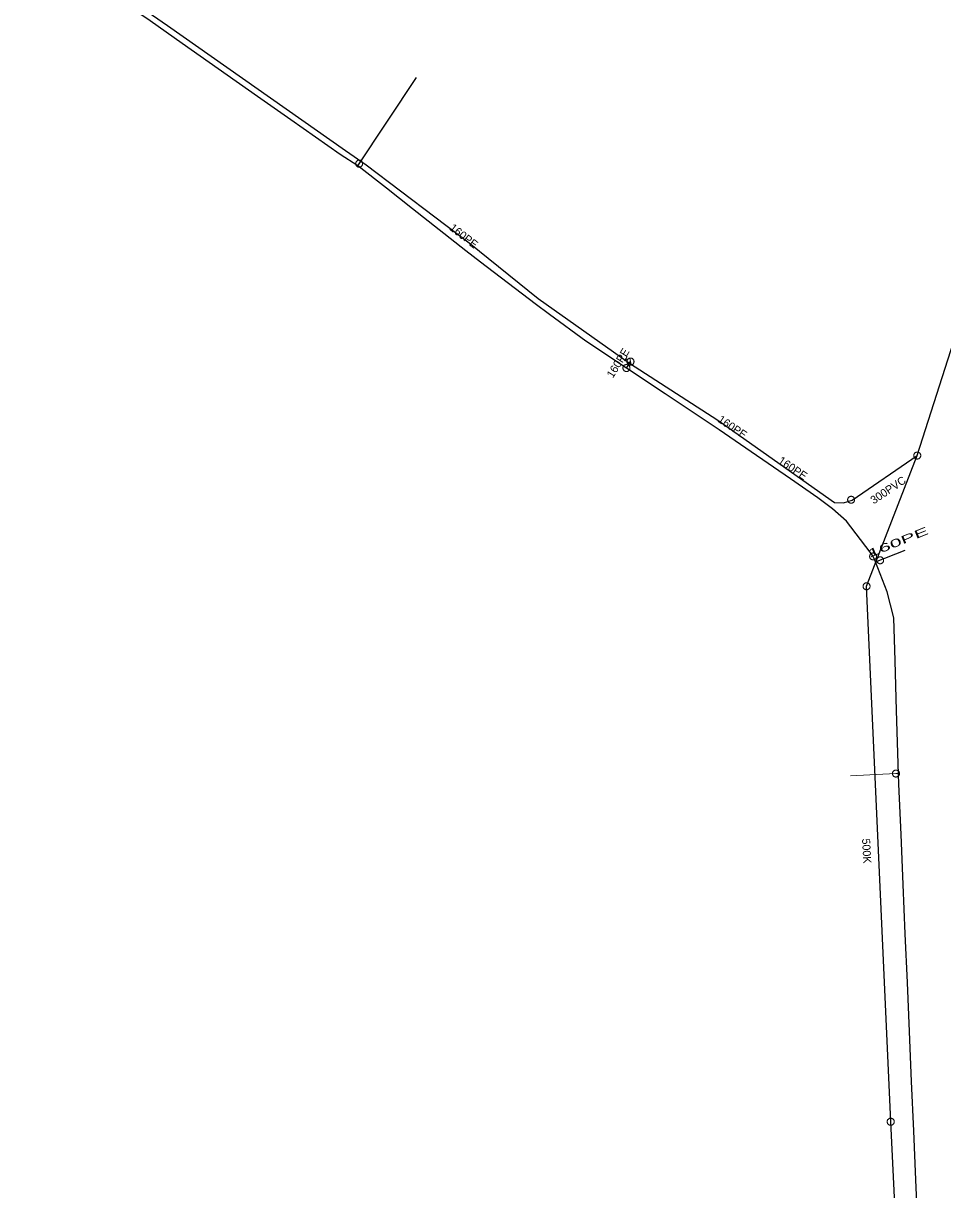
# Model space of a CAD drawing. Extents: x -741806 to -738704, y -1059275 to -1055387.
# Drawn here: x -740278.7 to -740163.8, y -1056238.7 to -1056093 of the extents above; entities that cross this region are included whole.
import ezdxf

# ---------------------------------------------------------------- set-up
doc = ezdxf.new("R2010")
doc.units = 0
doc.header["$LTSCALE"] = 0.4
for name, color, linetype, lineweight in [('2', 7, 'Continuous', 25), ('21', 7, 'Continuous', 13), ('3', 7, 'Continuous', 13), ('50', 7, 'Continuous', 13), ('51', 7, 'Continuous', 13), ('52', 7, 'Continuous', 25)]:
    doc.layers.add(name, color=color, linetype=linetype, lineweight=lineweight)
doc.layers.add('5', color=7, linetype='Continuous')
doc.layers.add('53', color=7, linetype='Continuous')

msp = doc.modelspace()

# ---------------------------------------------------------------- linework, layer by layer
at = {"layer": '2'}
msp.add_line((-740175.09, -1056152.54), (-740166.94, -1056146.97), dxfattribs=at)
for points in [[(-740347.69, -1055992.02), (-740330.71, -1056025.94), (-740324.879, -1056035.399), (-740312.55, -1056051.09), (-740298.309, -1056065.56), (-740282.969, -1056077.85), (-740260.67, -1056093.22), (-740238.399, -1056108.84), (-740235.84, -1056110.649), (-740222.969, -1056120.379), (-740214.329, -1056127.35), (-740202.93, -1056135.429), (-740191.883, -1056142.544), (-740177.289, -1056152.83), (-740176.145, -1056152.872), (-740175.09, -1056152.54)], [(-740156.993, -1056330.193), (-740165.539, -1056330.419), (-740167.3, -1056291.23), (-740170.26, -1056230.22), (-740173.28, -1056163.31), (-740166.94, -1056146.97), (-740157.149, -1056116.429)]]:
    msp.add_lwpolyline(points, dxfattribs=at)
at = {"layer": '21'}
msp.add_lwpolyline([(-740169.288, -1056186.703), (-740169.602, -1056186.713), (-740175.287, -1056187.003)], dxfattribs=at)
at = {"layer": '3'}
for points in [[(-740166.502, -1056146.97), (-740166.504, -1056146.925), (-740166.512, -1056146.88), (-740166.524, -1056146.835), (-740166.539, -1056146.793), (-740166.561, -1056146.752), (-740166.585, -1056146.713), (-740166.615, -1056146.678), (-740166.647, -1056146.645), (-740166.683, -1056146.617), (-740166.72, -1056146.592), (-740166.762, -1056146.571), (-740166.804, -1056146.554), (-740166.848, -1056146.543), (-740166.894, -1056146.535), (-740166.94, -1056146.533), (-740166.985, -1056146.535), (-740167.031, -1056146.543), (-740167.075, -1056146.554), (-740167.117, -1056146.571), (-740167.159, -1056146.592), (-740167.196, -1056146.617), (-740167.232, -1056146.645), (-740167.264, -1056146.678), (-740167.294, -1056146.713), (-740167.318, -1056146.752), (-740167.338, -1056146.793), (-740167.355, -1056146.835), (-740167.367, -1056146.88), (-740167.375, -1056146.925), (-740167.377, -1056146.971), (-740167.375, -1056147.016), (-740167.367, -1056147.061), (-740167.355, -1056147.106), (-740167.338, -1056147.149), (-740167.318, -1056147.189), (-740167.294, -1056147.228), (-740167.264, -1056147.263), (-740167.232, -1056147.296), (-740167.196, -1056147.324), (-740167.159, -1056147.349), (-740167.117, -1056147.37), (-740167.075, -1056147.387), (-740167.031, -1056147.399), (-740166.985, -1056147.406), (-740166.94, -1056147.408), (-740166.894, -1056147.406), (-740166.848, -1056147.399), (-740166.804, -1056147.387), (-740166.762, -1056147.37), (-740166.72, -1056147.349), (-740166.683, -1056147.324), (-740166.647, -1056147.296), (-740166.615, -1056147.263), (-740166.585, -1056147.228), (-740166.561, -1056147.189), (-740166.539, -1056147.148), (-740166.524, -1056147.106), (-740166.512, -1056147.061), (-740166.504, -1056147.016), (-740166.502, -1056146.971)], [(-740174.768, -1056152.5), (-740174.771, -1056152.455), (-740174.778, -1056152.41), (-740174.79, -1056152.365), (-740174.806, -1056152.323), (-740174.827, -1056152.282), (-740174.852, -1056152.243), (-740174.881, -1056152.208), (-740174.913, -1056152.175), (-740174.949, -1056152.147), (-740174.987, -1056152.122), (-740175.028, -1056152.101), (-740175.071, -1056152.084), (-740175.115, -1056152.073), (-740175.16, -1056152.065), (-740175.206, -1056152.063), (-740175.252, -1056152.065), (-740175.297, -1056152.073), (-740175.341, -1056152.084), (-740175.384, -1056152.101), (-740175.425, -1056152.122), (-740175.463, -1056152.147), (-740175.498, -1056152.175), (-740175.531, -1056152.208), (-740175.56, -1056152.243), (-740175.585, -1056152.282), (-740175.605, -1056152.323), (-740175.622, -1056152.365), (-740175.634, -1056152.41), (-740175.641, -1056152.455), (-740175.643, -1056152.501), (-740175.641, -1056152.546), (-740175.634, -1056152.591), (-740175.622, -1056152.636), (-740175.605, -1056152.679), (-740175.585, -1056152.719), (-740175.56, -1056152.758), (-740175.531, -1056152.793), (-740175.498, -1056152.826), (-740175.463, -1056152.854), (-740175.425, -1056152.879), (-740175.384, -1056152.9), (-740175.341, -1056152.917), (-740175.297, -1056152.929), (-740175.252, -1056152.936), (-740175.206, -1056152.938), (-740175.16, -1056152.936), (-740175.115, -1056152.929), (-740175.071, -1056152.917), (-740175.028, -1056152.9), (-740174.987, -1056152.879), (-740174.949, -1056152.854), (-740174.913, -1056152.826), (-740174.881, -1056152.793), (-740174.852, -1056152.758), (-740174.827, -1056152.719), (-740174.806, -1056152.678), (-740174.79, -1056152.636), (-740174.778, -1056152.591), (-740174.771, -1056152.546), (-740174.768, -1056152.501)], [(-740172.842, -1056163.31), (-740172.845, -1056163.265), (-740172.852, -1056163.22), (-740172.864, -1056163.175), (-740172.88, -1056163.133), (-740172.901, -1056163.092), (-740172.926, -1056163.053), (-740172.955, -1056163.018), (-740172.987, -1056162.985), (-740173.023, -1056162.957), (-740173.061, -1056162.932), (-740173.102, -1056162.911), (-740173.145, -1056162.894), (-740173.189, -1056162.883), (-740173.234, -1056162.875), (-740173.28, -1056162.873), (-740173.326, -1056162.875), (-740173.371, -1056162.883), (-740173.415, -1056162.894), (-740173.458, -1056162.911), (-740173.499, -1056162.932), (-740173.537, -1056162.957), (-740173.572, -1056162.985), (-740173.605, -1056163.018), (-740173.634, -1056163.053), (-740173.659, -1056163.092), (-740173.679, -1056163.133), (-740173.696, -1056163.175), (-740173.708, -1056163.22), (-740173.715, -1056163.265), (-740173.717, -1056163.311), (-740173.715, -1056163.356), (-740173.708, -1056163.401), (-740173.696, -1056163.446), (-740173.679, -1056163.489), (-740173.659, -1056163.529), (-740173.634, -1056163.568), (-740173.605, -1056163.603), (-740173.572, -1056163.636), (-740173.537, -1056163.664), (-740173.499, -1056163.689), (-740173.458, -1056163.71), (-740173.415, -1056163.727), (-740173.371, -1056163.739), (-740173.326, -1056163.746), (-740173.28, -1056163.748), (-740173.234, -1056163.746), (-740173.189, -1056163.739), (-740173.145, -1056163.727), (-740173.102, -1056163.71), (-740173.061, -1056163.689), (-740173.023, -1056163.664), (-740172.987, -1056163.636), (-740172.955, -1056163.603), (-740172.926, -1056163.568), (-740172.901, -1056163.529), (-740172.88, -1056163.488), (-740172.864, -1056163.446), (-740172.852, -1056163.401), (-740172.845, -1056163.356), (-740172.842, -1056163.311)], [(-740169.822, -1056230.22), (-740169.825, -1056230.175), (-740169.832, -1056230.13), (-740169.844, -1056230.085), (-740169.86, -1056230.043), (-740169.881, -1056230.002), (-740169.906, -1056229.963), (-740169.935, -1056229.928), (-740169.967, -1056229.895), (-740170.003, -1056229.867), (-740170.041, -1056229.842), (-740170.082, -1056229.821), (-740170.125, -1056229.804), (-740170.169, -1056229.793), (-740170.214, -1056229.785), (-740170.26, -1056229.783), (-740170.306, -1056229.785), (-740170.351, -1056229.793), (-740170.395, -1056229.804), (-740170.438, -1056229.821), (-740170.479, -1056229.842), (-740170.517, -1056229.867), (-740170.552, -1056229.895), (-740170.585, -1056229.928), (-740170.614, -1056229.963), (-740170.639, -1056230.002), (-740170.659, -1056230.043), (-740170.676, -1056230.085), (-740170.688, -1056230.13), (-740170.695, -1056230.175), (-740170.697, -1056230.221), (-740170.695, -1056230.266), (-740170.688, -1056230.311), (-740170.676, -1056230.356), (-740170.659, -1056230.399), (-740170.639, -1056230.439), (-740170.614, -1056230.478), (-740170.585, -1056230.513), (-740170.552, -1056230.546), (-740170.517, -1056230.574), (-740170.479, -1056230.599), (-740170.438, -1056230.62), (-740170.395, -1056230.637), (-740170.351, -1056230.649), (-740170.306, -1056230.656), (-740170.26, -1056230.658), (-740170.214, -1056230.656), (-740170.169, -1056230.649), (-740170.125, -1056230.637), (-740170.082, -1056230.62), (-740170.041, -1056230.599), (-740170.003, -1056230.574), (-740169.967, -1056230.546), (-740169.935, -1056230.513), (-740169.906, -1056230.478), (-740169.881, -1056230.439), (-740169.86, -1056230.398), (-740169.844, -1056230.356), (-740169.832, -1056230.311), (-740169.825, -1056230.266), (-740169.822, -1056230.221)]]:
    msp.add_lwpolyline(points, dxfattribs=at)
at = {"layer": '50'}
for p, q in [((-740203.547, -1056135.127), (-740203.384, -1056134.865)), ((-740203.222, -1056134.605), (-740203.384, -1056134.865)), ((-740203.171, -1056134.998), (-740203.384, -1056134.865)), ((-740202.792, -1056135.234), (-740202.89, -1056134.801)), ((-740202.792, -1056135.234), (-740202.69, -1056135.671))]:
    msp.add_line(p, q, dxfattribs=at)
msp.add_lwpolyline([(-740202.553, -1056134.859), (-740202.596, -1056134.836), (-740202.638, -1056134.816), (-740202.684, -1056134.802), (-740202.73, -1056134.794), (-740202.774, -1056134.789), (-740202.823, -1056134.79), (-740202.868, -1056134.796), (-740202.915, -1056134.806), (-740202.959, -1056134.82), (-740203, -1056134.841), (-740203.041, -1056134.864), (-740203.08, -1056134.89), (-740203.112, -1056134.924), (-740203.144, -1056134.959), (-740203.17, -1056134.996), (-740203.192, -1056135.037), (-740203.212, -1056135.078), (-740203.225, -1056135.124), (-740203.234, -1056135.17), (-740203.239, -1056135.218), (-740203.238, -1056135.263), (-740203.233, -1056135.31), (-740203.222, -1056135.355), (-740203.208, -1056135.399), (-740203.188, -1056135.443), (-740203.165, -1056135.483), (-740203.137, -1056135.519), (-740203.105, -1056135.556), (-740203.069, -1056135.584), (-740203.033, -1056135.614), (-740202.991, -1056135.636), (-740202.948, -1056135.654), (-740202.905, -1056135.667), (-740202.858, -1056135.678), (-740202.811, -1056135.681), (-740202.765, -1056135.682), (-740202.719, -1056135.675), (-740202.673, -1056135.666), (-740202.627, -1056135.65), (-740202.587, -1056135.631), (-740202.545, -1056135.606), (-740202.509, -1056135.578), (-740202.474, -1056135.549), (-740202.441, -1056135.511), (-740202.415, -1056135.474), (-740202.393, -1056135.433), (-740202.375, -1056135.39), (-740202.36, -1056135.345), (-740202.351, -1056135.3), (-740202.347, -1056135.252), (-740202.347, -1056135.207), (-740202.352, -1056135.159), (-740202.363, -1056135.115), (-740202.377, -1056135.071), (-740202.399, -1056135.029), (-740202.42, -1056134.987), (-740202.448, -1056134.95), (-740202.481, -1056134.917), (-740202.516, -1056134.886)], close=True, dxfattribs=at)
at = {"layer": '51'}
for points in [[(-740236.467, -1056110.131), (-740236.506, -1056110.108), (-740236.547, -1056110.089), (-740236.591, -1056110.074), (-740236.635, -1056110.064), (-740236.681, -1056110.058), (-740236.727, -1056110.058), (-740236.772, -1056110.062), (-740236.817, -1056110.071), (-740236.861, -1056110.085), (-740236.903, -1056110.103), (-740236.943, -1056110.126), (-740236.981, -1056110.152), (-740237.015, -1056110.182), (-740237.046, -1056110.216), (-740237.073, -1056110.253), (-740237.097, -1056110.292), (-740237.116, -1056110.334), (-740237.13, -1056110.377), (-740237.14, -1056110.422), (-740237.145, -1056110.468), (-740237.145, -1056110.513), (-740237.142, -1056110.559), (-740237.132, -1056110.604), (-740237.119, -1056110.647), (-740237.1, -1056110.69), (-740237.078, -1056110.73), (-740237.052, -1056110.766), (-740237.021, -1056110.801), (-740236.987, -1056110.832), (-740236.951, -1056110.86), (-740236.912, -1056110.882), (-740236.87, -1056110.902), (-740236.826, -1056110.916), (-740236.782, -1056110.926), (-740236.737, -1056110.932), (-740236.69, -1056110.932), (-740236.645, -1056110.928), (-740236.6, -1056110.919), (-740236.557, -1056110.905), (-740236.515, -1056110.887), (-740236.475, -1056110.865), (-740236.437, -1056110.838), (-740236.403, -1056110.808), (-740236.372, -1056110.775), (-740236.344, -1056110.737), (-740236.321, -1056110.698), (-740236.302, -1056110.656), (-740236.287, -1056110.613), (-740236.277, -1056110.568), (-740236.272, -1056110.522), (-740236.272, -1056110.477), (-740236.275, -1056110.431), (-740236.285, -1056110.386), (-740236.298, -1056110.343), (-740236.317, -1056110.3), (-740236.339, -1056110.26), (-740236.365, -1056110.224), (-740236.396, -1056110.189), (-740236.43, -1056110.158), (-740236.466, -1056110.131)], [(-740203.663, -1056135.798), (-740203.687, -1056135.836), (-740203.706, -1056135.878), (-740203.721, -1056135.922), (-740203.73, -1056135.966), (-740203.736, -1056136.011), (-740203.736, -1056136.058), (-740203.731, -1056136.103), (-740203.723, -1056136.148), (-740203.708, -1056136.191), (-740203.691, -1056136.233), (-740203.668, -1056136.273), (-740203.642, -1056136.311), (-740203.612, -1056136.346), (-740203.578, -1056136.376), (-740203.541, -1056136.403), (-740203.501, -1056136.427), (-740203.46, -1056136.446), (-740203.417, -1056136.46), (-740203.371, -1056136.47), (-740203.326, -1056136.475), (-740203.28, -1056136.475), (-740203.235, -1056136.472), (-740203.19, -1056136.462), (-740203.146, -1056136.449), (-740203.104, -1056136.43), (-740203.064, -1056136.408), (-740203.027, -1056136.381), (-740202.992, -1056136.351), (-740202.962, -1056136.317), (-740202.934, -1056136.28), (-740202.911, -1056136.241), (-740202.892, -1056136.2), (-740202.877, -1056136.156), (-740202.867, -1056136.112), (-740202.862, -1056136.066), (-740202.862, -1056136.02), (-740202.866, -1056135.974), (-740202.875, -1056135.929), (-740202.889, -1056135.886), (-740202.907, -1056135.844), (-740202.93, -1056135.804), (-740202.956, -1056135.766), (-740202.987, -1056135.733), (-740203.02, -1056135.701), (-740203.057, -1056135.674), (-740203.097, -1056135.65), (-740203.139, -1056135.632), (-740203.181, -1056135.617), (-740203.227, -1056135.607), (-740203.272, -1056135.602), (-740203.318, -1056135.602), (-740203.363, -1056135.605), (-740203.408, -1056135.615), (-740203.452, -1056135.628), (-740203.494, -1056135.647), (-740203.534, -1056135.67), (-740203.571, -1056135.696), (-740203.606, -1056135.727), (-740203.636, -1056135.76), (-740203.663, -1056135.797)], [(-740172.635, -1056159.18), (-740172.675, -1056159.2), (-740172.714, -1056159.225), (-740172.75, -1056159.254), (-740172.782, -1056159.286), (-740172.811, -1056159.322), (-740172.836, -1056159.361), (-740172.856, -1056159.402), (-740172.873, -1056159.444), (-740172.884, -1056159.488), (-740172.891, -1056159.533), (-740172.894, -1056159.579), (-740172.892, -1056159.626), (-740172.885, -1056159.671), (-740172.873, -1056159.715), (-740172.856, -1056159.757), (-740172.836, -1056159.799), (-740172.811, -1056159.837), (-740172.782, -1056159.872), (-740172.749, -1056159.904), (-740172.713, -1056159.933), (-740172.675, -1056159.958), (-740172.634, -1056159.979), (-740172.591, -1056159.995), (-740172.547, -1056160.007), (-740172.502, -1056160.014), (-740172.456, -1056160.017), (-740172.411, -1056160.014), (-740172.365, -1056160.007), (-740172.321, -1056159.995), (-740172.278, -1056159.979), (-740172.238, -1056159.958), (-740172.2, -1056159.933), (-740172.163, -1056159.904), (-740172.131, -1056159.872), (-740172.103, -1056159.836), (-740172.077, -1056159.797), (-740172.057, -1056159.757), (-740172.04, -1056159.714), (-740172.029, -1056159.67), (-740172.022, -1056159.625), (-740172.019, -1056159.579), (-740172.021, -1056159.533), (-740172.029, -1056159.488), (-740172.04, -1056159.444), (-740172.057, -1056159.401), (-740172.078, -1056159.36), (-740172.103, -1056159.322), (-740172.131, -1056159.286), (-740172.164, -1056159.254), (-740172.2, -1056159.225), (-740172.239, -1056159.2), (-740172.279, -1056159.179), (-740172.322, -1056159.163), (-740172.366, -1056159.151), (-740172.412, -1056159.144), (-740172.458, -1056159.141), (-740172.502, -1056159.144), (-740172.548, -1056159.151), (-740172.592, -1056159.163), (-740172.634, -1056159.18)], [(-740171.144, -1056160.06), (-740171.146, -1056160.015), (-740171.153, -1056159.97), (-740171.165, -1056159.925), (-740171.181, -1056159.883), (-740171.202, -1056159.842), (-740171.227, -1056159.803), (-740171.256, -1056159.768), (-740171.288, -1056159.735), (-740171.324, -1056159.707), (-740171.362, -1056159.682), (-740171.403, -1056159.661), (-740171.446, -1056159.644), (-740171.49, -1056159.632), (-740171.535, -1056159.625), (-740171.581, -1056159.623), (-740171.627, -1056159.625), (-740171.672, -1056159.632), (-740171.716, -1056159.644), (-740171.759, -1056159.661), (-740171.8, -1056159.682), (-740171.838, -1056159.707), (-740171.874, -1056159.735), (-740171.906, -1056159.768), (-740171.935, -1056159.803), (-740171.96, -1056159.842), (-740171.981, -1056159.883), (-740171.997, -1056159.925), (-740172.009, -1056159.97), (-740172.016, -1056160.015), (-740172.019, -1056160.061), (-740172.016, -1056160.106), (-740172.009, -1056160.151), (-740171.997, -1056160.196), (-740171.981, -1056160.238), (-740171.96, -1056160.279), (-740171.935, -1056160.318), (-740171.906, -1056160.353), (-740171.874, -1056160.386), (-740171.838, -1056160.414), (-740171.8, -1056160.439), (-740171.759, -1056160.46), (-740171.716, -1056160.477), (-740171.672, -1056160.488), (-740171.627, -1056160.496), (-740171.581, -1056160.498), (-740171.535, -1056160.496), (-740171.49, -1056160.488), (-740171.446, -1056160.477), (-740171.403, -1056160.46), (-740171.362, -1056160.439), (-740171.324, -1056160.414), (-740171.288, -1056160.386), (-740171.256, -1056160.353), (-740171.227, -1056160.318), (-740171.202, -1056160.279), (-740171.181, -1056160.238), (-740171.165, -1056160.196), (-740171.153, -1056160.151), (-740171.146, -1056160.106), (-740171.144, -1056160.061)], [(-740170.027, -1056186.614), (-740170.035, -1056186.658), (-740170.039, -1056186.704), (-740170.037, -1056186.75), (-740170.031, -1056186.795), (-740170.02, -1056186.84), (-740170.004, -1056186.883), (-740169.984, -1056186.924), (-740169.96, -1056186.963), (-740169.931, -1056186.999), (-740169.899, -1056187.031), (-740169.864, -1056187.061), (-740169.826, -1056187.087), (-740169.786, -1056187.109), (-740169.744, -1056187.126), (-740169.699, -1056187.138), (-740169.654, -1056187.146), (-740169.609, -1056187.15), (-740169.563, -1056187.148), (-740169.517, -1056187.141), (-740169.473, -1056187.129), (-740169.43, -1056187.114), (-740169.389, -1056187.094), (-740169.35, -1056187.069), (-740169.314, -1056187.042), (-740169.281, -1056187.009), (-740169.251, -1056186.974), (-740169.226, -1056186.937), (-740169.204, -1056186.896), (-740169.188, -1056186.853), (-740169.174, -1056186.809), (-740169.167, -1056186.765), (-740169.164, -1056186.719), (-740169.165, -1056186.673), (-740169.172, -1056186.628), (-740169.183, -1056186.583), (-740169.199, -1056186.54), (-740169.219, -1056186.499), (-740169.243, -1056186.46), (-740169.272, -1056186.425), (-740169.303, -1056186.392), (-740169.338, -1056186.362), (-740169.376, -1056186.336), (-740169.417, -1056186.315), (-740169.459, -1056186.297), (-740169.503, -1056186.285), (-740169.549, -1056186.277), (-740169.594, -1056186.275), (-740169.64, -1056186.275), (-740169.685, -1056186.282), (-740169.73, -1056186.294), (-740169.773, -1056186.309), (-740169.814, -1056186.329), (-740169.853, -1056186.354), (-740169.889, -1056186.381), (-740169.922, -1056186.414), (-740169.951, -1056186.449), (-740169.976, -1056186.486), (-740169.998, -1056186.527), (-740170.015, -1056186.57), (-740170.027, -1056186.613)]]:
    msp.add_lwpolyline(points, dxfattribs=at)
at = {"layer": '52'}
for p, q in [((-740236.879, -1056110.75), (-740229.55, -1056099.73)), ((-740233.298, -1056113.574), (-740236.879, -1056110.75)), ((-740203.3, -1056136.04), (-740202.796, -1056135.232)), ((-740172.16, -1056160.25), (-740168.441, -1056158.777))]:
    msp.add_line(p, q, dxfattribs=at)
for points in [[(-740236.879, -1056110.75), (-740239.1, -1056109.35), (-740245.267, -1056105.01), (-740249.432, -1056102.08), (-740254.321, -1056098.641), (-740258.843, -1056095.46), (-740262.849, -1056092.663), (-740268.245, -1056088.922), (-740273.022, -1056085.61), (-740277.315, -1056082.634), (-740283.48, -1056078.36)], [(-740203.3, -1056136.04), (-740208.359, -1056132.69), (-740212.897, -1056129.349), (-740214.69, -1056128.03), (-740221.537, -1056122.798), (-740223.375, -1056121.393), (-740230.027, -1056116.153), (-740233.298, -1056113.574)], [(-740172.16, -1056160.25), (-740172.458, -1056159.58), (-740172.84, -1056159.03), (-740175.78, -1056155.169), (-740177.528, -1056153.633), (-740179.373, -1056152.237), (-740182.787, -1056149.89), (-740187.717, -1056146.506), (-740191.718, -1056143.761), (-740198.462, -1056139.246), (-740203.3, -1056136.04)], [(-740166.82, -1056244.154), (-740167.11, -1056237.469), (-740167.374, -1056231.371), (-740167.642, -1056225.201), (-740167.914, -1056218.933), (-740168.179, -1056212.823), (-740168.443, -1056206.737), (-740168.706, -1056200.565), (-740168.967, -1056194.345), (-740169.233, -1056188.053), (-740169.286, -1056186.786), (-740169.528, -1056178.825), (-740169.717, -1056172.605), (-740169.879, -1056167.26), (-740170.719, -1056163.982), (-740172.16, -1056160.25)]]:
    msp.add_lwpolyline(points, dxfattribs=at)

# ---------------------------------------------------------------- texts
at = {"layer": '5'}
for s, rotation, p in [('300PVC', 34, (-740172.37, -1056153.086)), ('500K', 273, (-740173.842, -1056194.855))]:
    msp.add_text(s, height=1, rotation=rotation, dxfattribs=at).set_placement(p)
at = {"layer": '53'}
for rotation, p in [(322, (-740225.517, -1056118.687)), (58, (-740204.994, -1056137.367)), (326, (-740191.977, -1056142.693)), (326, (-740184.44, -1056147.838))]:
    msp.add_text('160PE ', height=1, rotation=rotation, dxfattribs=at).set_placement(p)
at = {"layer": '53', "width": 2}
msp.add_text('160PE ', height=1, rotation=22, dxfattribs=at).set_placement((-740172.895, -1056159.749))

doc.saveas('drawing.dxf')
